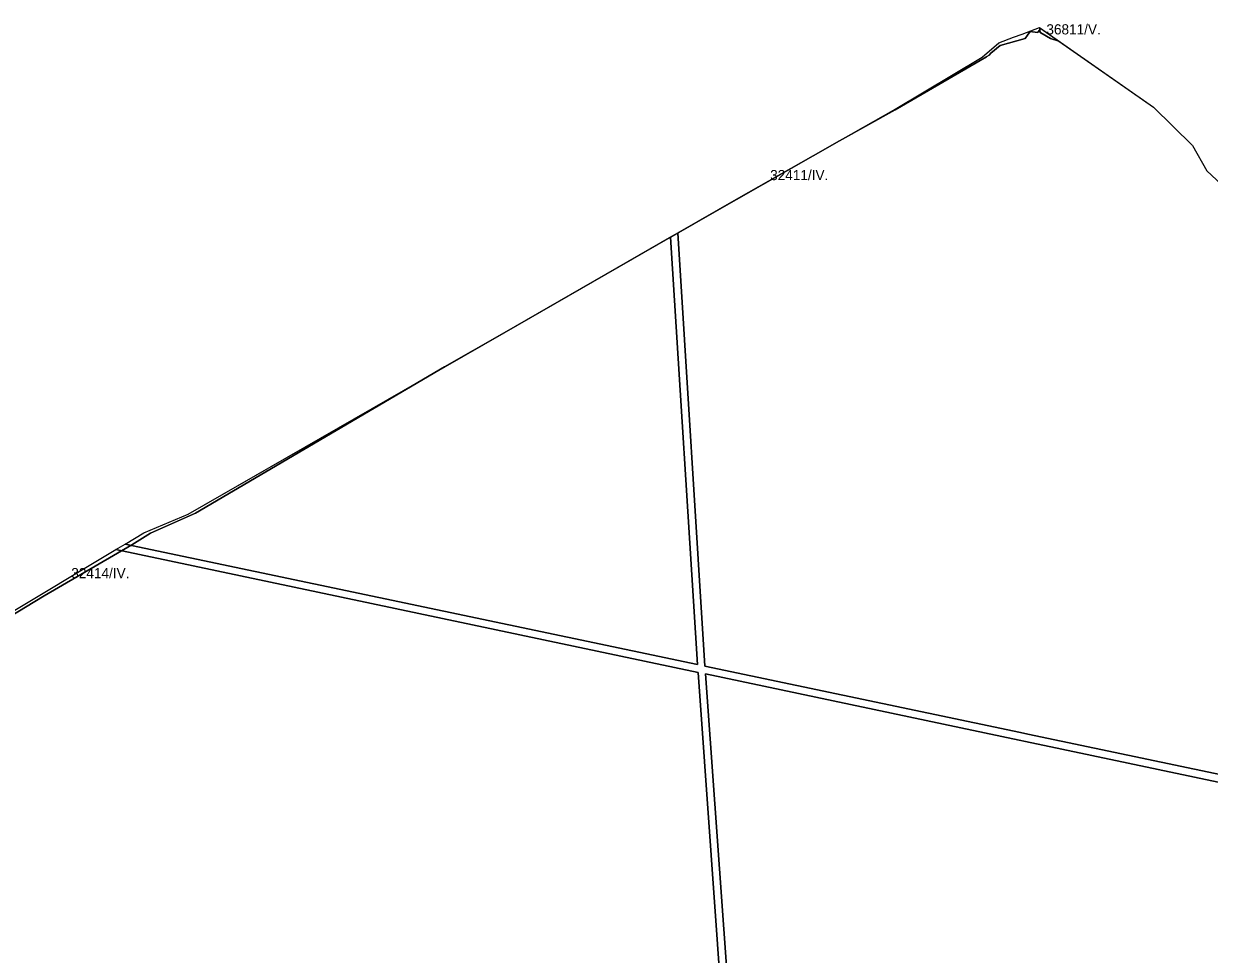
# Model space of a CAD drawing. Extents: x -535894 to -532834, y -1165802 to -1163645.
# Drawn here: x -535071 to -534487, y -1164103 to -1163645 of the extents above; entities that cross this region are included whole.
import ezdxf

# ---------------------------------------------------------------- set-up
doc = ezdxf.new("R2010")
doc.units = 0
doc.layers.add('95620013', color=7, linetype='Continuous')
doc.layers.add('95660013', color=7, linetype='Continuous')

msp = doc.modelspace()

# ---------------------------------------------------------------- linework, layer by layer
at = {"layer": '95620013'}
for points in [[(-534579.5, -1163650.15), (-534570.98, -1163646.93), (-534514.86, -1163686.14), (-534495.67, -1163705.05), (-534488.62, -1163717.48), (-534476.78, -1163728.4), (-534459.7, -1163738.33), (-534445.87, -1163741.61), (-534431.31, -1163750.05), (-534428.93, -1164025.8), (-534576.69, -1163994.7), (-534580.33, -1163993.93), (-534735.68, -1163961.24), (-534749.05, -1163747.99), (-534718.97, -1163730.71), (-534642.84, -1163687.62), (-534599.15, -1163661.49), (-534591.03, -1163654.51), (-534583.72, -1163651.75)], [(-534752.66, -1163750.06), (-534739.26, -1163960.49), (-535021.19, -1163901.16), (-535011.93, -1163895.61), (-534990.07, -1163886.45)], [(-534735.42, -1163965.07), (-534580.94, -1163997.64), (-534577.82, -1163998.3), (-534429.37, -1164029.61), (-534426.3, -1164271.96), (-534439.05, -1164259.47), (-534446.52, -1164256.91), (-534458.72, -1164249.64), (-534465.85, -1164242.8), (-534477.05, -1164227.75), (-534492.39, -1164221.02), (-534521.68, -1164205.56), (-534554.26, -1164192.45), (-534591.23, -1164182.82), (-534594.62, -1164181.93), (-534604.82, -1164180.29), (-534627.51, -1164173.48), (-534643.92, -1164165.11), (-534663.32, -1164170.6), (-534682.2, -1164171.34), (-534689.58, -1164178.65), (-534705.88, -1164181.51), (-534719.55, -1164186.71)]]:
    msp.add_lwpolyline(points, close=True, dxfattribs=at)
for points in [[(-534429.37, -1164029.61), (-534577.82, -1163998.3), (-534580.94, -1163997.64), (-534735.42, -1163965.07), (-534719.55, -1164186.71), (-534723.07, -1164188.05), (-534739, -1163964.32), (-535025.69, -1163903.86), (-535021.19, -1163901.16), (-534739.26, -1163960.49), (-534752.66, -1163750.06), (-534749.05, -1163747.99), (-534735.68, -1163961.24), (-534580.33, -1163993.93), (-534576.69, -1163994.7), (-534428.93, -1164025.8)], [(-535193.05, -1164004.23), (-535025.69, -1163903.86), (-534739, -1163964.32), (-534723.07, -1164188.05), (-534730.44, -1164190.85), (-534748.83, -1164193.12), (-534781.14, -1164187.86), (-534780.04, -1164184.13), (-534779.41, -1164181.96), (-534833.11, -1164171.65), (-534856.69, -1164168.25), (-534859.37, -1164167.86), (-534900.73, -1164174.23), (-534917.74, -1164173.57), (-534951.85, -1164167.07), (-534993.44, -1164171.93), (-534993.22, -1164184.39), (-534995, -1164182.89), (-535007.7, -1164178.2), (-535037.17, -1164175.56), (-535077.79, -1164162.19)]]:
    msp.add_lwpolyline(points, dxfattribs=at)
at = {"layer": '95660013'}
for points in [[(-535123.09, -1163964.15), (-535060.95, -1163926.6), (-535017.814, -1163901.521), (-535008.66, -1163895.82), (-534986.45, -1163886.01), (-534863.837, -1163813.99), (-534863.824, -1163813.983), (-534834.57, -1163797.178), (-534752.117, -1163749.813), (-534748.506, -1163747.74), (-534733.08, -1163738.88), (-534669.42, -1163702.738), (-534641.998, -1163687.404), (-534596.99, -1163661.322), (-534596.89, -1163661.239), (-534595.689, -1163660.58), (-534594.955, -1163659.625), (-534590.404, -1163655.831), (-534578.054, -1163652.262), (-534576.833, -1163650.635), (-534575.583, -1163648.967), (-534571.892, -1163649.356), (-534570.875, -1163648), (-534570.594, -1163649.492), (-534570.37, -1163649.516), (-534565.465, -1163652.41), (-534561.475, -1163653.571), (-534514.86, -1163686.14), (-534495.67, -1163705.05), (-534488.62, -1163717.48), (-534476.78, -1163728.4)], [(-535193.05, -1164004.23), (-535025.69, -1163903.86), (-535021.19, -1163901.16), (-535011.93, -1163895.61), (-534990.07, -1163886.45), (-534834.589, -1163797.128), (-534834.57, -1163797.178), (-534863.824, -1163813.983), (-534863.837, -1163813.99), (-534986.45, -1163886.01), (-535008.66, -1163895.82), (-535017.814, -1163901.521), (-535060.95, -1163926.6), (-535123.09, -1163964.15)]]:
    msp.add_lwpolyline(points, dxfattribs=at)
for points in [[(-534570.772, -1163647.075), (-534570.875, -1163648), (-534571.892, -1163649.356), (-534575.583, -1163648.967), (-534576.833, -1163650.635), (-534578.054, -1163652.262), (-534590.404, -1163655.831), (-534594.955, -1163659.625), (-534595.689, -1163660.58), (-534596.89, -1163661.239), (-534596.99, -1163661.322), (-534641.998, -1163687.404), (-534669.42, -1163702.738), (-534733.08, -1163738.88), (-534748.506, -1163747.74), (-534752.117, -1163749.813), (-534834.57, -1163797.178), (-534834.589, -1163797.128), (-534752.66, -1163750.06), (-534749.05, -1163747.99), (-534718.97, -1163730.71), (-534642.84, -1163687.62), (-534599.15, -1163661.49), (-534591.03, -1163654.51), (-534583.72, -1163651.75), (-534579.5, -1163650.15), (-534570.98, -1163646.93)], [(-534561.475, -1163653.571), (-534565.465, -1163652.41), (-534570.37, -1163649.516), (-534570.594, -1163649.492), (-534570.875, -1163648), (-534570.772, -1163647.075)]]:
    msp.add_lwpolyline(points, close=True, dxfattribs=at)

# ---------------------------------------------------------------- texts
for s, rotation, p in [('36811/V.', 360, (-534567.563, -1163650.323)), ('32411/IV.', 0, (-534703.56, -1163722.054)), ('32414/IV.', 360, (-535047.649, -1163917.962))]:
    msp.add_text(s, height=5, rotation=rotation, dxfattribs=at).set_placement(p)

doc.saveas('drawing.dxf')
